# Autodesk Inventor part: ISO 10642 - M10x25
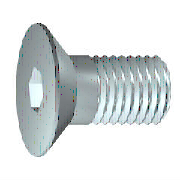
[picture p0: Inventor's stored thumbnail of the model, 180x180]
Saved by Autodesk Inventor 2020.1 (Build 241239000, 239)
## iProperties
Created: 2019-01
Part Number: ISO 10642 - M10x25
Material: Stahl, weich
Description: Senkschrauben mit Innensechskant
Document SubType Name: Modeling
Standard: ISO 10642
Designer: lutzd
Standards Organization: ISO
Language: de-DE
Size Designation: M10x25
Categories: <MemberInstance><Categories><Category DisplayName="Verbindungselemente" InternalName="e4da775c-781d-43d5-af7c-5136215cf5a6" Mnemonic="FSTN"><Category DisplayNam
Mass: 19.3071 g
Surface Area: 14.4621 cm^2
Volume: 2.4595 cm^3
Density: 7.85 g/cm^3
Appearance: Halbpoliert
IsCustomPart: 0
Author: lutzd
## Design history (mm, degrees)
node "WorkPoint1"
sketch "Skizze2"
  geometry: L1 (-5, -25)-(0, -25); L2 (-5, -5.5)-(-5, -25); L3 (-10, -0.5)-(-5, -5.5); L4 (-10, 0)-(-10, -0.5); L5 (0, 0)-(-10, 0); L6 (0, -25)-(0, 0); L7 (0, -25)-(0, 0); L8 (0, -30)-(0, 5) reference; L9 (2, 0)-(-12, 0) reference
  constraints: 14 end point, 3 vertical, 2 horizontal
  dimensions: "d3" = 10 distance of L5.start L4.start (= 0.5 x dk); "d5" = 5 distance of L1.start L1.end (= 0.5 x NND); "d7" = 25 distance of L1.end L5.start (= NLG); "ParC" = 0.5 distance of L4.start L3.start; "d22" = 0 distance between parallel lines of L8 L6; "d23" = 0 distance between parallel lines of L9 L5; "d43" = 45 deg angle of L6 L3 (= 0.5 x ang)
revolve "Drehung1" stored, may be unused: angle "d8" = 360 deg
node "MSC_A1"
node "MSC_PF1"
node "MSC_PT1"
body "Solid1"
node "Skizze1"
sketch "Skizze3"
  geometry: L1 (-3, 1.732)-(-3, -1.732); L2 (0, 3.464)-(-3, 1.732); L3 (3, 1.732)-(0, 3.464); L4 (3, -1.732)-(3, 1.732); L5 (0, -3.464)-(3, -1.732); L6 (-3, -1.732)-(0, -3.464); C1 r 3 at (0, 0); C2 r 5 at (0, 0) reference
  constraints: 12 end point, 6 tangent, 2 parallel, 2 vertical, 1 centre point, 1 concentric
  dimensions: "d11" = 6 diameter of C1 (= ParS); "d13" = 120 deg angle of L1 L2; "d15" = 120 deg angle of L6 L1
extrude "Extrusion1" cut sketch "Skizze3" distance "d16" = 4.4 (= ParT); taper "d17" = 0 deg
fillet "Rundung1" dims "d18" = 0.5 (= r)
chamfer "Fase1" distance "d19" = 0.75 (= 0.5 x PTC); stored, may be unused: angle "d20" = 45 deg, second distance "d39" = 0.75 (= 0.5 x PTC)
feature "Gewinde1" dims "d35" = 0, "b" = 16.5
other parameters: "PTC" = 1.5 [user parameter; used in 2 equation terms], "ParK" = 5.5 [user parameter], "ParS" = 6 [user parameter; used in 1 equation term], "ParT" = 4.4 [user parameter; used in 1 equation term], "r" = 0.5 [user parameter; used in 1 equation term], "NLG" = 25 [user parameter; used in 1 equation term], "d0" = 45 deg (derived), "d2" = 3 (derived), "d4" = 1.5 (derived), "d6" = 8 (derived), "d9" = 0, "d10" = 2 (derived), "d12" = 120 deg (derived), "d14" = 120 deg (derived), "d37" = 0, "d38" = 0, "d40" = 0, "d41" = 0, "d42" = 0, "ang" = 90 deg [user parameter; used in 1 equation term]
